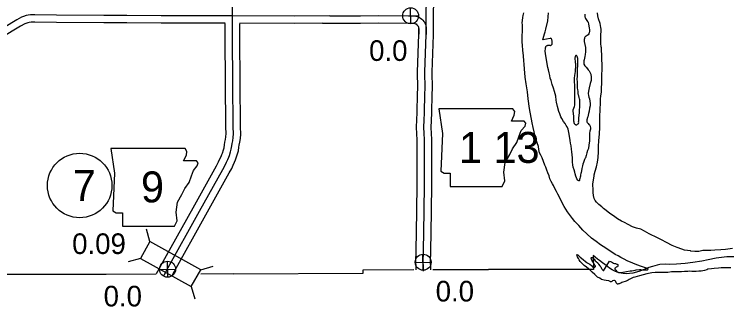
# Model space of a CAD drawing. Extents: x 31699 to 244310, y -8841 to 11474.
# Drawn here: x 99993 to 100967, y 1624 to 2024 of the extents above; entities that cross this region are included whole.
import ezdxf

# ---------------------------------------------------------------- set-up
doc = ezdxf.new("R2010")
doc.units = 0
for name, color, linetype in [('B_Logo', 7, 'Continuous'), ('G-ANNO-TEXT', 7, 'Continuous'), ('Level 21', 7, 'Continuous'), ('R_Border Notes', 7, 'Continuous'), ('R_Draft', 7, 'Continuous'), ('R_Logo', 7, 'Continuous'), ('R_XS_EARTHWORK_STAGE1', 7, 'Continuous'), ('R_XS_EARTHWORK_STAGE2', 7, 'Continuous'), ('S_WALL', 7, 'Continuous'), ('S_WALL_ANNOT', 7, 'Continuous')]:
    doc.layers.add(name, color=color, linetype=linetype)

msp = doc.modelspace()

# ---------------------------------------------------------------- linework, layer by layer
at = {"layer": 'B_Logo'}
for points in [[(100555.08, 1995.98), (100557.13, 2293.76)], [(100200.75, 1673.7), (100245.69, 1754.56), (100277.65, 1811.66), (100280.74, 1817.45), (100282.7, 1821.77), (100284.39, 1825.37), (100285.6, 1828.43), (100286.48, 1830.63), (100287.98, 1835.56), (100289, 1839.23), (100289.69, 1843.7), (100290.31, 1846.9), (100291.07, 1850.71), (100291.69, 1855.11), (100292.19, 1860.25), (100291.92, 1869.74), (100291.38, 1930.73), (100290.91, 1990.65), (100290.64, 2021.18), (100290.5, 2082.96)], [(100423.52, 2021.53), (100375.77, 2021.12), (100290.64, 2021.18), (100193.47, 2021.31), (100146.65, 2021.9), (100115.39, 2021.98), (100050.75, 2022.29), (100020.89, 2022.7), (100015.04, 2022.61), (100011.71, 2022.1), (100009.25, 2021.65), (100005.38, 2020.6), (100002.98, 2019.55), (99996.37, 2015.72), (99942.09, 1983.37)], [(100423.52, 2021.53), (100465.29, 2021.44)], [(100465.29, 2021.44), (100489.61, 2021.65), (100531.01, 2021.59), (100536.74, 2021.17), (100539.67, 2021.27), (100541.2, 2021.02), (100542.93, 2020.5), (100544.6, 2019.85), (100545.94, 2019.19), (100547.28, 2018.27), (100549.23, 2016.69), (100550.44, 2015.43), (100551.78, 2013.78), (100552.79, 2012.52), (100553.54, 2010.59), (100554.02, 2009.59), (100554.5, 2007.66), (100554.92, 2006.06), (100555.13, 2004.46), (100555.21, 2003.06), (100555.08, 1995.98)], [(100551.07, 1682.01), (100552.03, 1724.47), (100552.69, 1789.38), (100552.86, 1841.66), (100552.69, 1852.87), (100552.29, 1860.15), (100552.13, 1869.69), (100552.52, 1878.44), (100552.95, 1889.6), (100553.31, 1914.24), (100553.83, 1922.66), (100553.43, 1944.62), (100555.08, 1995.98)], [(100551.07, 1682.01), (100551, 1672.85)], [(100200.75, 1673.7), (100196.92, 1666.87)]]:
    msp.add_lwpolyline(points, dxfattribs=at)
at = {"layer": 'G-ANNO-TEXT'}
for points in [[(100572.17, 1894.6), (100577.25, 1860.76), (100574.99, 1809.44), (100579.5, 1806.62), (100587.96, 1806.62), (100587.96, 1788.58), (100659.02, 1788.58), (100662.4, 1795.91), (100661.27, 1807.75), (100662.96, 1821.29), (100669.17, 1832), (100673.11, 1839.89), (100678.75, 1848.35), (100682.14, 1857.38), (100684.96, 1864.71), (100690.03, 1870.91), (100691.16, 1874.86), (100688.9, 1877.68), (100671.42, 1877.68), (100675.37, 1885.57), (100675.93, 1890.65), (100673.6, 1894.55)], [(100124.86, 1840.28), (100129.93, 1806.44), (100127.68, 1755.12), (100132.19, 1752.3), (100140.65, 1752.3), (100140.65, 1734.26), (100211.7, 1734.26), (100215.08, 1741.59), (100213.96, 1753.43), (100215.65, 1766.97), (100221.85, 1777.68), (100225.8, 1785.58), (100231.44, 1794.04), (100234.82, 1803.06), (100237.64, 1810.39), (100242.72, 1816.59), (100243.85, 1820.54), (100241.59, 1823.36), (100224.11, 1823.36), (100228.06, 1831.25), (100228.62, 1836.33), (100226.28, 1840.23)]]:
    msp.add_lwpolyline(points, close=True, dxfattribs=at)
at = {"layer": 'Level 21'}
for p, q in [((100534.14, 2010.62), (100533.64, 2032.32)), ((100523.04, 2021.22), (100544.74, 2021.72)), ((100551.22, 1674.12), (100550.72, 1695.82)), ((100202.42, 1664.57), (100201.92, 1686.27)), ((100540.12, 1684.72), (100561.82, 1685.22)), ((100191.32, 1675.17), (100213.02, 1675.67))]:
    msp.add_line(p, q, dxfattribs=at)
for centre in [(100533.89, 2021.47), (100550.97, 1684.97), (100202.17, 1675.42)]:
    msp.add_circle(centre, 10.85, dxfattribs=at)
at = {"layer": 'R_Border Notes'}
msp.add_circle((100082.24, 1789.76), 44, dxfattribs=at)
at = {"layer": 'R_Draft'}
for points in [[(100723.92, 1798.92), (100722.82, 1803.11), (100721.12, 1807.1), (100719.75, 1810.49), (100718.32, 1814.75), (100717.09, 1817.74), (100715.25, 1822.67), (100713.27, 1827.45), (100711.44, 1830.98), (100709.61, 1834.56), (100708.77, 1838.69), (100708.2, 1843.03), (100706.62, 1848.16), (100705.18, 1852.55), (100703.6, 1858.27), (100702.42, 1863.14), (100701.3, 1869.14), (100699.98, 1875.13), (100695.94, 1894.66), (100694.41, 1908.06), (100693.19, 1917.6), (100691.62, 1928.67), (100690.41, 1937.8), (100689.82, 1943.74), (100689.37, 1948.74), (100688.71, 1955.21), (100688.4, 1959.88), (100687.81, 1966.69), (100687.07, 1974.29), (100686.41, 1981.03), (100686.3, 1985.7), (100686.18, 1991.38), (100686.21, 1995.45), (100686.37, 1999.12), (100686.51, 2005.4), (100686.35, 2008.87), (100686.32, 2011.87), (100686.42, 2015.08), (100686.98, 2018.96), (100687.56, 2021.77), (100688.26, 2025.38)], [(100714.16, 1988.44), (100715.58, 1993.73), (100716.54, 1997.01), (100717.45, 1999.42), (100718.28, 2003.04), (100720.97, 2014.75), (100722.2, 2025.44)], [(100782.61, 1791.73), (100783.51, 1797.36), (100784.19, 1802.57), (100784.51, 1804.38), (100785.79, 1809.33), (100787.47, 1815.09), (100788.94, 1821.44), (100789.81, 1827.86), (100790.27, 1835.68), (100790.4, 1842.89), (100790.66, 1850.97), (100791.44, 1859.73), (100791.95, 1869.48), (100792.01, 1877.23), (100792.03, 1882.7), (100792.38, 1894.59), (100792.91, 1901.81), (100793.19, 1907.95), (100793.49, 1911.83), (100794.23, 1917.58), (100794.51, 1922.99), (100794.72, 1929.2), (100794.75, 1933.14), (100794.84, 1937.95), (100795.06, 1942.62), (100795.16, 1946.16), (100795.25, 1950.77), (100795.14, 1955.78), (100794.95, 1961.05), (100794.77, 1966.99), (100794.68, 1969.59), (100794.51, 1972.66), (100794.5, 1974.53), (100794.48, 1975.93), (100794.54, 1976.67), (100794.4, 1977.87), (100794.12, 1979.2), (100793.84, 1980.53), (100793.62, 1982.4), (100793.39, 1985.67), (100793.36, 1988.74), (100793.46, 1993.02), (100793.63, 1996.42), (100793.73, 1999.5), (100793.76, 2003.1), (100793.54, 2005.57), (100793.12, 2008.24), (100792.42, 2011.1), (100790.37, 2017.42), (100789.47, 2021.29), (100788.89, 2025.49)], [(100771.8, 2023.72), (100771.74, 2022.99), (100771.69, 2021.58), (100771.7, 2021.05), (100771.84, 2019.91), (100772.05, 2018.92), (100772.46, 2017.85), (100773.6, 2016.53), (100774.55, 2015.07), (100775.42, 2013.81), (100776.17, 2012.55), (100776.46, 2009.88), (100777.77, 2004.82), (100778, 2002.15), (100777.88, 2000.54), (100777.57, 1998.07), (100777.18, 1996.6), (100776.26, 1995.45), (100773.62, 1993.49), (100772.49, 1993.08), (100771.83, 1992.41), (100771.18, 1991.33), (100770.98, 1990.46), (100770.87, 1988.92)], [(100724.52, 1990.61), (100714.16, 1988.44)], [(100754.5, 1831.59), (100753.99, 1835.86), (100753.36, 1839.39), (100752.79, 1843.93), (100752.22, 1847.53), (100751.72, 1851.2), (100750.8, 1857.33), (100749.89, 1862.26), (100748.92, 1866.46), (100747.75, 1869.72), (100746.34, 1871.78), (100744.72, 1874.23), (100742.49, 1877.15), (100740.06, 1881.13), (100738.84, 1883.65), (100737.34, 1887.45), (100736.24, 1890.97), (100734.38, 1897.63), (100733.2, 1903.3), (100732.57, 1906.23), (100731.85, 1911.9), (100730.46, 1917.89), (100729.02, 1922.55), (100727.24, 1927.61), (100725.53, 1933), (100724.56, 1936.46), (100723.67, 1940.06), (100722.83, 1943.66), (100722, 1947.52), (100721.23, 1950.99), (100720.32, 1955.99), (100719.89, 1959.19), (100719.05, 1964.25), (100718.49, 1967.05), (100717.8, 1969.58), (100717.29, 1973.58), (100717.8, 1976.13), (100717.99, 1977.73), (100718.44, 1979), (100718.64, 1979.54), (100719.3, 1980.28), (100720.02, 1980.75), (100720.49, 1981.03), (100721.02, 1981.23), (100721.15, 1981.3), (100721.81, 1981.51), (100723.35, 1981.19), (100724.48, 1981), (100724.81, 1981.07), (100725.21, 1981.27), (100725.67, 1981.48), (100726.07, 1981.68), (100726.34, 1981.88), (100726.67, 1982.15), (100726.86, 1982.69), (100726.92, 1983.49), (100727.04, 1984.63), (100727.17, 1985.63), (100727.09, 1986.43), (100726.95, 1987.23), (100726.74, 1988.1), (100726.47, 1989.16), (100726.06, 1989.89), (100725.52, 1990.56), (100725.19, 1990.82), (100724.52, 1990.61)], [(100770.87, 1988.92), (100770.95, 1986.46), (100772.63, 1978.26), (100772.72, 1975.19), (100772.55, 1972.25), (100772.19, 1968.57), (100771.81, 1965.97), (100771.3, 1963.56), (100770.66, 1961.28), (100770.41, 1959.81), (100770.22, 1958), (100770.31, 1956.34), (100770.45, 1955.47), (100771.47, 1953.21), (100773.35, 1951.16), (100775.23, 1949.24), (100776.37, 1947.85), (100777.45, 1946.39), (100778.47, 1944.6), (100779.63, 1941.74), (100779.76, 1941.47), (100780.46, 1937.94), (100780.48, 1935.47), (100780.17, 1933.2), (100779.15, 1928.85), (100777.54, 1923.29), (100776.52, 1918.61), (100776.45, 1918.47), (100776.22, 1915.13), (100776.64, 1912.66), (100777.19, 1910.27), (100777.81, 1908.2), (100778.51, 1904.87), (100778.8, 1901.74), (100778.7, 1898.73), (100778.2, 1895.45), (100777.37, 1891.31), (100776.6, 1888.03), (100775.58, 1883.61), (100775.26, 1882.4), (100774.55, 1879.59), (100774.3, 1878.46), (100774.3, 1877.86), (100774.38, 1877.05), (100774.51, 1876.46), (100774.79, 1875.79), (100775.26, 1875.19), (100776.13, 1874.33), (100777.27, 1873.14), (100778.01, 1872.35), (100778.48, 1871.82), (100778.83, 1870.82), (100779.03, 1870.09), (100779.18, 1868.42), (100779.27, 1866.49), (100778.69, 1863.88), (100778.18, 1861.2), (100778.01, 1858.19), (100777.97, 1855.39), (100778, 1852.79), (100777.82, 1850.25), (100777.27, 1845.43), (100776.45, 1840.42), (100775.48, 1837.61), (100774.24, 1834.26), (100773.41, 1830.71), (100772.44, 1827.69), (100772.31, 1827.23), (100771.33, 1825.15), (100769.64, 1821.19), (100768.86, 1818.78), (100768.42, 1816.64), (100767.65, 1813.09), (100767.15, 1809.88), (100766.71, 1807.61), (100766.25, 1806.13), (100765.81, 1804.26), (100765.55, 1802.59), (100765.17, 1800.92), (100764.85, 1799.38), (100764.53, 1798.11), (100764.4, 1797.44), (100764.34, 1796.77), (100764.28, 1796.63), (100764.02, 1796.3), (100763.82, 1796.16), (100763.35, 1796.22), (100762.55, 1796.68), (100761.88, 1797.21), (100760.87, 1798.67), (100760.25, 1800.33), (100759.43, 1802.53), (100758.34, 1805.52), (100757.85, 1807.86), (100756.89, 1811.05), (100755.86, 1814.71), (100755.43, 1817.85), (100754.93, 1821.45), (100754.83, 1824.92), (100754.67, 1827.72), (100754.5, 1831.59)], [(100761.89, 1874), (100762.56, 1874.14), (100762.95, 1874.54), (100763.28, 1875.28), (100763.13, 1876.55), (100763.32, 1878.08), (100763.43, 1879.75), (100763.61, 1882.29), (100764.15, 1888.77), (100764.26, 1891.04), (100764.57, 1893.59), (100764.88, 1896.39), (100764.91, 1899.8), (100764.89, 1902), (100764.93, 1904.34), (100764.86, 1905.47), (100764.71, 1906.74), (100764.37, 1908.14), (100763.75, 1909.87), (100763.26, 1912.2), (100763.12, 1913.2), (100762.64, 1915.13), (100762.41, 1918.14), (100761.92, 1920.67), (100761.63, 1922.8), (100761.54, 1925.2), (100761.44, 1928.74), (100761.48, 1931.61), (100761.39, 1934.42), (100761.41, 1939.29), (100761.52, 1942.43), (100761.55, 1946.3), (100761.65, 1949.31), (100762.02, 1952.85), (100762.25, 1956.46), (100762.29, 1959.13), (100762.28, 1960.87), (100762.13, 1962.47), (100761.92, 1963.33), (100761.71, 1964.4), (100761.16, 1965.86), (100760.76, 1966.86), (100760.35, 1967.46), (100759.82, 1967.45), (100759.15, 1967.18), (100758.89, 1966.71), (100758.5, 1965.7), (100758.06, 1963.43), (100758.07, 1962.03), (100758.36, 1959.49), (100758.65, 1957.63), (100758.86, 1956.49), (100758.94, 1954.62), (100758.7, 1951.35), (100758.53, 1948.34), (100758.29, 1945.6), (100757.68, 1940.12), (100757.31, 1936.31), (100757.15, 1932.11), (100757.41, 1925.63), (100757.53, 1920.42), (100757.46, 1913.55), (100757.37, 1908.67), (100757.54, 1905.34), (100757.5, 1902.33), (100757.32, 1899.99), (100757.01, 1897.18), (100756.04, 1895.04), (100755.46, 1892.56), (100755.47, 1891.56), (100755.64, 1887.76), (100756.27, 1884.36), (100756.29, 1882.62), (100756.24, 1879.88), (100756.33, 1877.81), (100756.54, 1876.68), (100756.68, 1876.08), (100756.82, 1875.42), (100757.16, 1874.75), (100757.29, 1874.49), (100757.63, 1874.02), (100758.03, 1873.69), (100758.57, 1873.23), (100758.91, 1872.9), (100759.31, 1872.7), (100759.71, 1872.71), (100760.24, 1872.71), (100760.5, 1872.78)], [(100760.5, 1872.78), (100761.89, 1874)], [(100812.64, 1675.68), (100813.76, 1673.98), (100814.67, 1672.81), (100816.3, 1671.86), (100817.18, 1671.43), (100818.05, 1671.19), (100819.19, 1671.09), (100821.32, 1671.03), (100828.61, 1672.22), (100833.58, 1673.06), (100835.64, 1673.4), (100838.02, 1673.82), (100840.34, 1674.36), (100841.72, 1674.74), (100846.04, 1675.09), (100847.98, 1674.96), (100850.65, 1674.72), (100853.05, 1674.74), (100854.19, 1674.71), (100855.72, 1674.63), (100856.39, 1674.65), (100857.18, 1674.81), (100857.77, 1675.17), (100858.16, 1675.45), (100858.22, 1675.71), (100857.47, 1676.02), (100855.65, 1676.83), (100852.88, 1677.87), (100849.1, 1679.21), (100842.69, 1681.52), (100837.03, 1683.6), (100829.38, 1687.08), (100825.11, 1689.2), (100820.9, 1691.39), (100817.03, 1693.53), (100813.09, 1695.73), (100809.9, 1697.62), (100804.99, 1700.86), (100800.08, 1704.16), (100793, 1708.66), (100786.91, 1713.33), (100780.69, 1717.92), (100774.36, 1723.91), (100768.86, 1728.87), (100763.59, 1734.96), (100758.13, 1740.79), (100754.94, 1744.75), (100748.11, 1753.6), (100743.25, 1761.18), (100741.05, 1765.38), (100737.76, 1772.08), (100734.97, 1777.72), (100732.77, 1781.72), (100730.84, 1785.6), (100728.77, 1789.6), (100727.42, 1791.96), (100725.51, 1795.3), (100723.92, 1798.92)], [(100973.15, 1703.93), (100963.48, 1702.19), (100957.43, 1701.78), (100949.18, 1701.3), (100943.39, 1701.23), (100936.53, 1701.06), (100932.87, 1700.8), (100927.38, 1699.81), (100921.59, 1699.54), (100916.23, 1700.29), (100916.03, 1700.42), (100907.46, 1701.59), (100904.08, 1702.95), (100897.54, 1705.26), (100890.72, 1707.89), (100883.12, 1712.04), (100876.34, 1715.48), (100870.64, 1718.29), (100859.46, 1723.98), (100853.28, 1727.44), (100847.86, 1729.93), (100842.01, 1731.46), (100836.48, 1733.54), (100830.72, 1736.35), (100825.56, 1739.04), (100821.56, 1741.24), (100816.33, 1744.2), (100810.6, 1748.21), (100805.81, 1751.65), (100800.95, 1755.49), (100796.99, 1758.49), (100794.92, 1760.42), (100790.6, 1764.02), (100787.44, 1766.91), (100785.77, 1769.06), (100784.4, 1772.02), (100783.54, 1775.99), (100783.14, 1779.99), (100782.89, 1785.26), (100782.75, 1789.53), (100782.61, 1791.73)], [(100816.73, 1655.18), (100816.13, 1655.16), (100815.64, 1655.61), (100814.89, 1656.25), (100814.53, 1657.04), (100813.96, 1658.29), (100813.74, 1658.88), (100813.25, 1659.54), (100812.29, 1660.1), (100811.16, 1660.13), (100809.31, 1659.67), (100808.34, 1658.83), (100807.63, 1658.21), (100806.83, 1658.04), (100806.01, 1658.62), (100804.39, 1659.43), (100800.97, 1659.98), (100797.95, 1660.48), (100794.59, 1661.56), (100791.93, 1663.27), (100788.75, 1664.77), (100785.36, 1668.26), (100781.72, 1671.6), (100779.38, 1673.86), (100776.44, 1676.16), (100773.77, 1678.21), (100770.83, 1680.45), (100767.52, 1683.6), (100765.5, 1686.21), (100764.03, 1688.36), (100762.97, 1690.06), (100761.76, 1692.42), (100761.18, 1693.94), (100760.88, 1694.8), (100760.87, 1695.26), (100761.32, 1695.55), (100762.2, 1695.11), (100765.38, 1691.88), (100769.36, 1688.54), (100772.5, 1686.05), (100774.15, 1684.77), (100774.9, 1684.13), (100776.86, 1683.26), (100778.5, 1682.25), (100780.76, 1680.32), (100782.08, 1678.76), (100782.49, 1678.44), (100783.16, 1678.27), (100783.83, 1678.09), (100784.36, 1678.17), (100784.7, 1678.25), (100785.29, 1678.34), (100785.68, 1678.55), (100785.99, 1679.23), (100786.04, 1679.77), (100785.48, 1680.82), (100783.91, 1683.7), (100782.29, 1686.39), (100781.3, 1687.95), (100780.66, 1689.27), (100780.36, 1690.13), (100780.41, 1690.8), (100780.72, 1691.41), (100780.98, 1691.55), (100781.31, 1691.63), (100781.85, 1691.45), (100782.95, 1690.48), (100784.2, 1689.12), (100785.86, 1687.11), (100787.17, 1685.82), (100789.17, 1684.02), (100790.42, 1682.52), (100792.16, 1680.18), (100793.41, 1678.55), (100794.48, 1676.65), (100794.77, 1675.93), (100795.47, 1674.95), (100796.02, 1674.37), (100796.57, 1673.92), (100796.91, 1673.67), (100797.26, 1673.34), (100805.28, 1686.51), (100807.85, 1685.33), (100809.27, 1684.58), (100810.96, 1683.84), (100812.11, 1683.41), (100813.45, 1683.05), (100815.34, 1682.52), (100815.55, 1682.32), (100816.56, 1681.89), (100816.84, 1681.37), (100816.8, 1680.76), (100816.68, 1680.29), (100816.7, 1679.62), (100816.13, 1678.87), (100815.4, 1678.65), (100814.54, 1678.48), (100813.44, 1677.58), (100812.74, 1676.68), (100812.62, 1676.08), (100812.64, 1675.68)], [(100971.05, 1677.34), (100965.78, 1677.36), (100960.65, 1677.51), (100957.78, 1677.48), (100954, 1677.08), (100948.22, 1676.48), (100944.31, 1675.88), (100939.53, 1675.38), (100938.22, 1674.54), (100935.06, 1673.56), (100930.28, 1672.79), (100927.22, 1672.75), (100923.43, 1672.56), (100921.11, 1672.28), (100917.7, 1672.36), (100914.76, 1672.59), (100912.3, 1672.51), (100907.58, 1672.21), (100903.59, 1672.07), (100899.59, 1671.93), (100894.53, 1672.03), (100889.94, 1671.73), (100884.83, 1671.09), (100878.63, 1671.14), (100873.9, 1671.18), (100867.77, 1670.97), (100863.05, 1670.67), (100860.67, 1670.12), (100856.3, 1669.17), (100846.47, 1666.23), (100842.91, 1665.3), (100839.73, 1664.72), (100837.74, 1664.32), (100835.77, 1663.39), (100832.11, 1661.46), (100830.74, 1660.61), (100828.9, 1659.67), (100828.05, 1659.18), (100826.66, 1658.86), (100823.37, 1657.75), (100822.19, 1657.24), (100820.88, 1656.53), (100819.63, 1655.88), (100818.31, 1655.57), (100817.38, 1655.4), (100816.73, 1655.18)]]:
    msp.add_lwpolyline(points, dxfattribs=at)
at = {"layer": 'R_Logo'}
for points in [[(100881.18, 1682.45), (100874.07, 1681.87), (100870.36, 1681.08), (100863.96, 1679.25), (100859.08, 1677.68), (100855.86, 1676.57), (100851.12, 1674.74), (100846.91, 1672.99), (100842.3, 1671.36), (100837.01, 1670.17), (100832.44, 1669.48), (100828.25, 1669.2), (100823.91, 1669.45), (100818.21, 1670.46), (100813.35, 1672.36), (100808.81, 1674.68), (100805.33, 1676.96), (100802.81, 1678.54), (100798.97, 1681.75), (100795.82, 1684.25), (100791.79, 1687.25), (100789.12, 1689.36), (100785.9, 1691.92), (100783.16, 1694.3), (100783.41, 1674.94), (100640.39, 1675.21)], [(100975, 1692.57), (100965.48, 1692.17), (100958.37, 1691.66), (100950.94, 1690.74), (100939.76, 1688.21), (100931.22, 1686.52), (100919.22, 1684.7), (100908.41, 1683.26), (100896.78, 1682.32), (100887.46, 1682), (100881.18, 1682.45)], [(100292.14, 1668.97), (100469.34, 1670.06), (100469.24, 1674.8), (100538.36, 1674.97)], [(100564.15, 1675.03), (100640.39, 1675.21)], [(100186.66, 1668.57), (100118.6, 1668.31), (99942.05, 1668.24), (99762.1, 1665.74), (99586.42, 1667.96), (99409.79, 1668.63), (99234.76, 1668.73)], [(100292.14, 1668.97), (100247.69, 1668.8)]]:
    msp.add_lwpolyline(points, dxfattribs=at)
at = {"layer": 'R_XS_EARTHWORK_STAGE1'}
for p, q in [((100178.16, 1713.31), (100173.32, 1730.23)), ((100178.16, 1713.31), (100165.33, 1690.23)), ((100247.39, 1674.84), (100178.16, 1713.31)), ((100165.33, 1690.23), (100148.41, 1685.4)), ((100165.33, 1690.23), (100234.56, 1651.76)), ((100234.56, 1651.76), (100247.39, 1674.84)), ((100247.39, 1674.84), (100264.31, 1679.67)), ((100234.56, 1651.76), (100239.4, 1634.84))]:
    msp.add_line(p, q, dxfattribs=at)
at = {"layer": 'R_XS_EARTHWORK_STAGE2'}
for points in [[(100565.08, 1995.91), (100567.08, 2287.22)], [(100280.64, 2011.19), (100193.4, 2011.31), (100146.58, 2011.9), (100115.36, 2011.98), (100050.66, 2012.29), (100020.9, 2012.7), (100015.88, 2012.62), (100013.37, 2012.23), (100011.45, 2011.88), (100008.71, 2011.14), (100007.51, 2010.62), (100001.44, 2007.1), (99946.05, 1974.08)], [(100192.01, 1678.56), (100236.95, 1759.44), (100268.87, 1816.46), (100271.77, 1821.87), (100273.62, 1825.96), (100275.2, 1829.34), (100276.31, 1832.14), (100277.04, 1833.94), (100278.37, 1838.36), (100279.21, 1841.35), (100279.84, 1845.42), (100280.5, 1848.83), (100281.21, 1852.39), (100281.76, 1856.3), (100282.18, 1860.59), (100281.92, 1869.55), (100281.38, 1930.64), (100280.91, 1990.56), (100280.73, 2011)], [(100209.49, 1668.84), (100254.42, 1749.69), (100286.42, 1806.86), (100289.72, 1813.02), (100291.78, 1817.59), (100293.57, 1821.4), (100294.89, 1824.73), (100295.93, 1827.32), (100297.58, 1832.77), (100298.79, 1837.12), (100299.54, 1841.99), (100300.12, 1844.98), (100300.93, 1849.03), (100301.63, 1853.92), (100302.21, 1859.91), (100301.92, 1869.92), (100301.38, 1930.81), (100300.91, 1990.73), (100300.73, 2011)], [(100413.53, 2011.44), (100375.81, 2011.12), (100300.88, 2011.17)], [(100413.53, 2011.55), (100465.27, 2011.44)], [(100465.38, 2011.44), (100489.64, 2011.65), (100530.64, 2011.59), (100536.54, 2011.16), (100538.99, 2011.24), (100539.68, 2011.03), (100540.58, 2010.68), (100540.88, 2010.54), (100541.28, 2010.26), (100542.44, 2009.32), (100542.94, 2008.8), (100544, 2007.49), (100544.03, 2007.46), (100544.36, 2006.62), (100544.56, 2006.19), (100544.81, 2005.19), (100545.09, 2004.13), (100545.17, 2003.51), (100545.21, 2002.87), (100545.08, 1996.17)], [(100545.08, 1996.05), (100545.15, 2006.19)], [(100541.07, 1682.24), (100542.03, 1724.63), (100542.69, 1789.44), (100542.86, 1841.6), (100542.7, 1852.52), (100542.29, 1859.79), (100542.13, 1869.83), (100542.53, 1878.85), (100542.95, 1889.86), (100543.32, 1914.62), (100543.83, 1922.87), (100543.43, 1944.69), (100545.08, 1996.3)], [(100561.07, 1681.78), (100562.03, 1724.31), (100562.69, 1789.31), (100562.86, 1841.72), (100562.69, 1853.22), (100562.29, 1860.5), (100562.14, 1869.55), (100562.51, 1878.03), (100562.94, 1889.33), (100563.31, 1913.86), (100563.84, 1922.44), (100563.43, 1944.55), (100565.07, 1995.66)], [(100192.03, 1678.59), (100186.66, 1669.01)], [(100541.07, 1682.08), (100541.02, 1674.84)], [(100561.07, 1681.94), (100561.02, 1674.84)], [(100209.47, 1668.81), (100208.02, 1666.22)]]:
    msp.add_lwpolyline(points, dxfattribs=at)

# ---------------------------------------------------------------- texts
at = {"layer": 'G-ANNO-TEXT'}
for s, p in [('1 13', (100599.93, 1820.63)), ('9', (100165.88, 1766.73))]:
    msp.add_text(s, height=42.24, dxfattribs=at).set_placement(p)
at = {"layer": 'R_Border Notes'}
msp.add_text('7', height=42.24, dxfattribs=at).set_placement((100072.79, 1768.64))
at = {"layer": 'S_WALL'}
msp.add_text('0.09', height=28.16, dxfattribs=at).set_placement((100071.99, 1696.23))
at = {"layer": 'S_WALL_ANNOT'}
for p in [(100477.24, 1959.85), (100568.07, 1631.41), (100114.9, 1624.65)]:
    msp.add_text('0.0', height=28.16, dxfattribs=at).set_placement(p)

doc.saveas('drawing.dxf')
